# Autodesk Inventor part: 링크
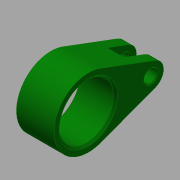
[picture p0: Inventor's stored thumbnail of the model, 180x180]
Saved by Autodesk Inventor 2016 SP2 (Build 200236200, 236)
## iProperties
Created: 2016-08
Part Number: 링크
Material: 강철, 탄소
Document SubType Name: Modeling
Designer: mduedu
Density: 7.87 g/cm^3
Appearance: 진녹색
Author: mduedu
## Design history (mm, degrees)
sketch "스케치1"
  geometry: L1 (32.1, 5.62)-(5.775, 15.456); L2 (32.1, -5.62)-(5.775, -15.456); C1 r 13 at (0, 0); C2 r 3 at (30, 0); A1 r 16.5 centre (0, 0) between (5.775, 15.456) and (5.775, -15.456); A2 r 6 centre (30, 0) between (32.1, 5.62) and (32.1, -5.62); 1 further point
  constraints: 4 centre point, 4 end point, 4 point on circle, 4 tangent, 3 coincident, 1 horizontal alignment
  dimensions: "d0" = 33 diameter of A1; "d2" = 12 diameter of A2; "d3" = 30 distance of A2.centre point (0, 0); "d4" = 26 diameter of C1; "d5" = 6 diameter of C2
extrude "돌출1" new body sketch "스케치1" stored distance "d6" = 18; taper "d7" = 0 deg
sketch "스케치2"
  geometry: L1 (-9, 36)-(9, 36) reference; L2 (0, 0)-(0, 36); L3 (-4, 36)-(4, 36); L4 (4, 36)-(4, 22); L5 (4, 22)-(-4, 22); L6 (-4, 22)-(-4, 36)
  constraints: 10 end point, 2 midpoint, 2 parallel, 1 horizontal, 1 perpendicular, 1 point on line
  dimensions: "d8" = 8 distance between parallel lines of L4 L6; "d10" = 14 distance of L3.end L4.end
extrude "돌출2" cut sketch "스케치2" stored distance "d11" = 20; taper "d12" = 0 deg
chamfer "모따기1" distance "d13" = 1; stored, may be unused: second distance "d14" = 2, angle "d15" = 45 deg
chamfer "모따기2" distance "d16" = 0.5; stored, may be unused: second distance "d17" = 2, angle "d18" = 45 deg
node "솔리드1"
